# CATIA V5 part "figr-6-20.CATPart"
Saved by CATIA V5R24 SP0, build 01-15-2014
Part number: Part1
Bounding box of the stored display mesh (mm): x 0 to 150, y -70 to 70, z -150 to 69.804
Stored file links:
  D:\KAVITA\CATIA V5-6R2014 Project_ Kavita\CATIA V5-6R2014_partfiles\Partfiles\c06_catia_v5-6r2014_prt\figr-6-20.CATPart
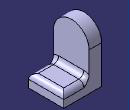
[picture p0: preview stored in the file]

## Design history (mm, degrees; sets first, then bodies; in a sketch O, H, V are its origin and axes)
Body1 (main body)
  Sketch1 on yz-plane, origin (0, 0, 0), H (0, 1, 0), V (0, 0, 1)
    arc A1 centre (0, 0) radius 70 from (70, 0) to (-70, 0) ccw
    point P1 (70, 0)
    point P2 (-70, 0)
    line L1 (-70, 0) -> (-70, -150)
    line L2 (-70, -150) -> (70, -150)
    line L3 (70, -150) -> (70, 0)
    construction circle A2 centre (0, 0) radius 37.5
    radius A1 = 70
    radius A2 = 37.5
    distance O L2 = 150
    coincidence: P1 H, P2 H
    tangency: L1 A1, L3 A1
    horizontal: L2 H
  Pad1: profile Sketch1, direction (1, 0, 0), length 50
  Sketch2 on face of Pad1, origin (50, 0, 0), H (0, 1, 0), V (0, 0, 1)
    line L1 (-70, -150) -> (70, -150)
    line L2 (70, -150) -> (70, -100)
    line L3 (70, -100) -> (-70, -100)
    line L4 (-70, -100) -> (-70, -150)
    reference projected line E1 (-70, -150) -> (70, -150) from edge [face of Pad1 | face of Pad1]
    reference projected line E2 (-70, 0) -> (-70, -150) from edge [face of Pad1 | face of Pad1]
    reference projected line E3 (70, -150) -> (70, 0) from edge [face of Pad1 | face of Pad1]
    length L2 = 50
    horizontal: L1 H, L3 H
    vertical: L2 V, L4 V
    coincidence: L1 E1, E2 L4, L2 E3
  Pad2: profile Sketch2, direction (1, 0, 0), length 100
  Fillet1: radius 20, on face of Pad2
